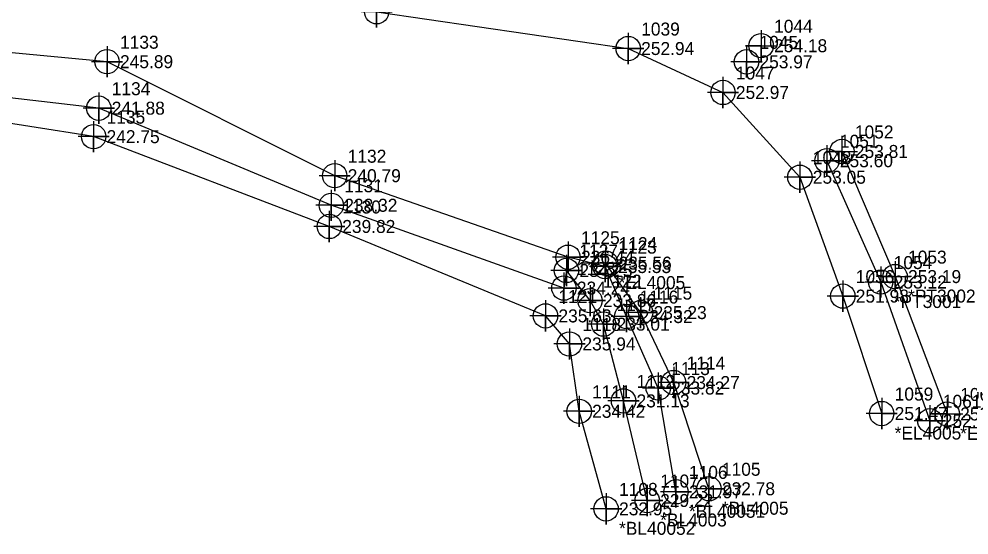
# Model space of a CAD drawing. Extents: x 2130962 to 2131465, y 643052 to 644206.
# Drawn here: x 2131077.2 to 2131260.2, y 643052.4 to 643151.7 of the extents above; entities that cross this region are included whole.
import ezdxf

# ---------------------------------------------------------------- set-up
doc = ezdxf.new("R2010")
doc.units = 0
for name, color, linetype in [('Exist DTM Breakline', 7, 'Continuous'), ('Exist DTM Breakline Cogo Comment', 7, 'Continuous'), ('Exist DTM Breakline Cogo Elevation', 7, 'Continuous'), ('Exist DTM Breakline Cogo Number', 7, 'Continuous'), ('Exist DTM Breakline Cogo Point CELL', 7, 'Continuous'), ('Exist DTM Drainline', 7, 'Continuous'), ('Exist DTM Drainline Cogo Comment', 7, 'Continuous'), ('Exist DTM Drainline Cogo Elevation', 7, 'Continuous'), ('Exist DTM Drainline Cogo Number', 7, 'Continuous'), ('Exist DTM Drainline Cogo Point CELL', 7, 'Continuous'), ('Exist Roads EOP', 7, 'Continuous'), ('Exist Roads EOP Cogo Comment', 7, 'Continuous'), ('Exist Roads EOP Cogo Elevation', 7, 'Continuous'), ('Exist Roads EOP Cogo Number', 7, 'Continuous'), ('Exist Roads EOP Cogo Point CELL', 7, 'Continuous'), ('Exist Roads EOT', 7, 'Continuous'), ('Exist Roads EOT Cogo Comment', 7, 'Continuous'), ('Exist Roads EOT Cogo Elevation', 7, 'Continuous'), ('Exist Roads EOT Cogo Number', 7, 'Continuous'), ('Exist Roads EOT Cogo Point CELL', 7, 'Continuous')]:
    doc.layers.add(name, color=color, linetype=linetype)

msp = doc.modelspace()

# ---------------------------------------------------------------- linework, layer by layer
at = {"layer": 'Exist DTM Breakline'}
for points in [[(2130997.5489, 643165.941), (2131045.6664, 643161.7962), (2131094.7686, 643157.2786), (2131146.0902, 643153.1147), (2131194.5413, 643146.0346), (2131212.7846, 643137.5737), (2131227.5943, 643121.2545), (2131235.8712, 643098.3644), (2131243.3589, 643075.7514)], [(2131203.7387, 643060.6768), (2131200.323, 643080.6622), (2131194.2334, 643094.4284), (2131190.0903, 643104.0511), (2131182.9576, 643105.8495), (2131138.023, 643121.5465), (2131094.1742, 643143.5026), (2131040.5455, 643148.5531), (2130995.6405, 643153.3049)], [(2131190.282, 643057.3997), (2131185.0957, 643076.1853), (2131183.224, 643089.154), (2131178.6092, 643094.5527), (2131136.9713, 643111.7747), (2131091.5821, 643129.064), (2131042.4244, 643136.794), (2130995.734, 643143.071)], [(2131210.0876, 643061.2695), (2131203.2966, 643081.7186), (2131196.9334, 643095.1899), (2131190.1951, 643104.7138)]]:
    msp.add_lwpolyline(points, dxfattribs=at)
at = {"layer": 'Exist DTM Breakline Cogo Point CELL'}
for points in [[(2131146.0902, 643156.1147), (2131146.0902, 643150.1147), (2131146.0902, 643153.1147), (2131149.0902, 643153.1147), (2131143.0902, 643153.1147)], [(2131194.5413, 643149.0346), (2131194.5413, 643143.0346), (2131194.5413, 643146.0346), (2131197.5413, 643146.0346), (2131191.5413, 643146.0346)], [(2131094.1742, 643146.5026), (2131094.1742, 643140.5026), (2131094.1742, 643143.5026), (2131097.1742, 643143.5026), (2131091.1742, 643143.5026)], [(2131212.7846, 643140.5737), (2131212.7846, 643134.5737), (2131212.7846, 643137.5737), (2131215.7846, 643137.5737), (2131209.7846, 643137.5737)], [(2131091.5821, 643132.064), (2131091.5821, 643126.064), (2131091.5821, 643129.064), (2131094.5821, 643129.064), (2131088.5821, 643129.064)], [(2131138.023, 643124.5465), (2131138.023, 643118.5465), (2131138.023, 643121.5465), (2131141.023, 643121.5465), (2131135.023, 643121.5465)], [(2131227.5943, 643124.2545), (2131227.5943, 643118.2545), (2131227.5943, 643121.2545), (2131230.5943, 643121.2545), (2131224.5943, 643121.2545)], [(2131136.9713, 643114.7747), (2131136.9713, 643108.7747), (2131136.9713, 643111.7747), (2131139.9713, 643111.7747), (2131133.9713, 643111.7747)], [(2131182.9576, 643108.8495), (2131182.9576, 643102.8495), (2131182.9576, 643105.8495), (2131185.9576, 643105.8495), (2131179.9576, 643105.8495)], [(2131190.0903, 643107.0511), (2131190.0903, 643101.0511), (2131190.0903, 643104.0511), (2131193.0903, 643104.0511), (2131187.0903, 643104.0511)], [(2131190.1951, 643107.7138), (2131190.1951, 643101.7138), (2131190.1951, 643104.7138), (2131193.1951, 643104.7138), (2131187.1951, 643104.7138)], [(2131235.8712, 643101.3644), (2131235.8712, 643095.3644), (2131235.8712, 643098.3644), (2131238.8712, 643098.3644), (2131232.8712, 643098.3644)], [(2131178.6092, 643097.5527), (2131178.6092, 643091.5527), (2131178.6092, 643094.5527), (2131181.6092, 643094.5527), (2131175.6092, 643094.5527)], [(2131194.2334, 643097.4284), (2131194.2334, 643091.4284), (2131194.2334, 643094.4284), (2131197.2334, 643094.4284), (2131191.2334, 643094.4284)], [(2131196.9334, 643098.1899), (2131196.9334, 643092.1899), (2131196.9334, 643095.1899), (2131199.9334, 643095.1899), (2131193.9334, 643095.1899)], [(2131183.224, 643092.154), (2131183.224, 643086.154), (2131183.224, 643089.154), (2131186.224, 643089.154), (2131180.224, 643089.154)], [(2131203.2966, 643084.7186), (2131203.2966, 643078.7186), (2131203.2966, 643081.7186), (2131206.2966, 643081.7186), (2131200.2966, 643081.7186)], [(2131200.323, 643083.6622), (2131200.323, 643077.6622), (2131200.323, 643080.6622), (2131203.323, 643080.6622), (2131197.323, 643080.6622)], [(2131185.0957, 643079.1853), (2131185.0957, 643073.1853), (2131185.0957, 643076.1853), (2131188.0957, 643076.1853), (2131182.0957, 643076.1853)], [(2131243.3589, 643078.7514), (2131243.3589, 643072.7514), (2131243.3589, 643075.7514), (2131246.3589, 643075.7514), (2131240.3589, 643075.7514)], [(2131210.0876, 643064.2695), (2131210.0876, 643058.2695), (2131210.0876, 643061.2695), (2131213.0876, 643061.2695), (2131207.0876, 643061.2695)], [(2131203.7387, 643063.6768), (2131203.7387, 643057.6768), (2131203.7387, 643060.6768), (2131206.7387, 643060.6768), (2131200.7387, 643060.6768)], [(2131190.282, 643060.3997), (2131190.282, 643054.3997), (2131190.282, 643057.3997), (2131193.282, 643057.3997), (2131187.282, 643057.3997)]]:
    msp.add_lwpolyline(points, dxfattribs=at)
for centre in [(2131146.0902, 643153.1147), (2131194.5413, 643146.0346), (2131094.1742, 643143.5026), (2131212.7846, 643137.5737), (2131091.5821, 643129.064), (2131138.023, 643121.5465), (2131227.5943, 643121.2545), (2131136.9713, 643111.7747), (2131182.9576, 643105.8495), (2131190.0903, 643104.0511), (2131190.1951, 643104.7138), (2131235.8712, 643098.3644), (2131196.9334, 643095.1899), (2131178.6092, 643094.5527), (2131194.2334, 643094.4284), (2131183.224, 643089.154), (2131200.323, 643080.6622), (2131203.2966, 643081.7186), (2131185.0957, 643076.1853), (2131243.3589, 643075.7514), (2131203.7387, 643060.6768), (2131210.0876, 643061.2695), (2131190.282, 643057.3997)]:
    msp.add_circle(centre, 2.344, dxfattribs=at)
at = {"layer": 'Exist DTM Drainline'}
msp.add_lwpolyline([(2131198.1997, 643059.006), (2131193.6429, 643078.1873), (2131189.8038, 643092.9639), (2131187.1852, 643097.4954), (2131182.6436, 643103.2956), (2131182.1533, 643099.9067), (2131137.3651, 643115.851), (2131092.5788, 643134.5516), (2131042.2635, 643140.3935), (2130996.1192, 643147.7639)], dxfattribs=at)
at = {"layer": 'Exist DTM Drainline Cogo Point CELL'}
for points in [[(2131092.5788, 643137.5516), (2131092.5788, 643131.5516), (2131092.5788, 643134.5516), (2131095.5788, 643134.5516), (2131089.5788, 643134.5516)], [(2131137.3651, 643118.851), (2131137.3651, 643112.851), (2131137.3651, 643115.851), (2131140.3651, 643115.851), (2131134.3651, 643115.851)], [(2131182.6436, 643106.2956), (2131182.6436, 643100.2956), (2131182.6436, 643103.2956), (2131185.6436, 643103.2956), (2131179.6436, 643103.2956)], [(2131182.1533, 643102.9067), (2131182.1533, 643096.9067), (2131182.1533, 643099.9067), (2131185.1533, 643099.9067), (2131179.1533, 643099.9067)], [(2131187.1852, 643100.4954), (2131187.1852, 643094.4954), (2131187.1852, 643097.4954), (2131190.1852, 643097.4954), (2131184.1852, 643097.4954)], [(2131189.8038, 643095.9639), (2131189.8038, 643089.9639), (2131189.8038, 643092.9639), (2131192.8038, 643092.9639), (2131186.8038, 643092.9639)], [(2131193.6429, 643081.1873), (2131193.6429, 643075.1873), (2131193.6429, 643078.1873), (2131196.6429, 643078.1873), (2131190.6429, 643078.1873)], [(2131198.1997, 643062.006), (2131198.1997, 643056.006), (2131198.1997, 643059.006), (2131201.1997, 643059.006), (2131195.1997, 643059.006)]]:
    msp.add_lwpolyline(points, dxfattribs=at)
for centre in [(2131092.5788, 643134.5516), (2131137.3651, 643115.851), (2131182.6436, 643103.2956), (2131182.1533, 643099.9067), (2131187.1852, 643097.4954), (2131189.8038, 643092.9639), (2131193.6429, 643078.1873), (2131198.1997, 643059.006)]:
    msp.add_circle(centre, 2.344, dxfattribs=at)
at = {"layer": 'Exist Roads EOP'}
msp.add_lwpolyline([(2131232.8113, 643124.4316), (2131243.1743, 643101.0702), (2131252.6325, 643074.3547)], dxfattribs=at)
at = {"layer": 'Exist Roads EOP Cogo Point CELL'}
for points in [[(2131217.3223, 643146.473), (2131217.3223, 643140.473), (2131217.3223, 643143.473), (2131220.3223, 643143.473), (2131214.3223, 643143.473)], [(2131232.8113, 643127.4316), (2131232.8113, 643121.4316), (2131232.8113, 643124.4316), (2131235.8113, 643124.4316), (2131229.8113, 643124.4316)], [(2131243.1743, 643104.0702), (2131243.1743, 643098.0702), (2131243.1743, 643101.0702), (2131246.1743, 643101.0702), (2131240.1743, 643101.0702)], [(2131252.6325, 643077.3547), (2131252.6325, 643071.3547), (2131252.6325, 643074.3547), (2131255.6325, 643074.3547), (2131249.6325, 643074.3547)]]:
    msp.add_lwpolyline(points, dxfattribs=at)
for centre in [(2131217.3223, 643143.473), (2131232.8113, 643124.4316), (2131243.1743, 643101.0702), (2131252.6325, 643074.3547)]:
    msp.add_circle(centre, 2.344, dxfattribs=at)
at = {"layer": 'Exist Roads EOT'}
msp.add_lwpolyline([(2131235.6934, 643126.2176), (2131245.9361, 643102.1206), (2131255.9743, 643075.6707)], dxfattribs=at)
at = {"layer": 'Exist Roads EOT Cogo Point CELL'}
for points in [[(2131220.1404, 643149.5724), (2131220.1404, 643143.5724), (2131220.1404, 643146.5724), (2131217.1404, 643146.5724), (2131223.1404, 643146.5724)], [(2131235.6934, 643129.2176), (2131235.6934, 643123.2176), (2131235.6934, 643126.2176), (2131232.6934, 643126.2176), (2131238.6934, 643126.2176)], [(2131245.9361, 643105.1206), (2131245.9361, 643099.1206), (2131245.9361, 643102.1206), (2131242.9361, 643102.1206), (2131248.9361, 643102.1206)], [(2131255.9743, 643078.6707), (2131255.9743, 643072.6707), (2131255.9743, 643075.6707), (2131252.9743, 643075.6707), (2131258.9743, 643075.6707)]]:
    msp.add_lwpolyline(points, dxfattribs=at)
for centre in [(2131220.1404, 643146.5724), (2131235.6934, 643126.2176), (2131245.9361, 643102.1206), (2131255.9743, 643075.6707)]:
    msp.add_circle(centre, 2.344, dxfattribs=at)

# ---------------------------------------------------------------- texts
at = {"layer": 'Exist DTM Breakline Cogo Comment'}
for s, p in [('*EL4005', (2131192.6951, 643099.7138)), ('*EL4005', (2131245.8589, 643070.7514)), ('*BL4005', (2131212.5876, 643056.2695)), ('*BL40051', (2131206.2387, 643055.6768)), ('*BL40052', (2131192.782, 643052.3997))]:
    msp.add_text(s, height=2.5, dxfattribs=at).set_placement(p)
at = {"layer": 'Exist DTM Breakline Cogo Elevation'}
for s, p in [('252.94', (2131197.0413, 643144.7846)), ('245.89', (2131096.6742, 643142.2526)), ('252.97', (2131215.2846, 643136.3237)), ('242.75', (2131094.0821, 643127.814)), ('240.79', (2131140.523, 643120.2965)), ('253.05', (2131230.0943, 643120.0045)), ('239.82', (2131139.4713, 643110.5247)), ('236.44', (2131185.4576, 643104.5995)), ('235.53', (2131192.5903, 643102.8011)), ('235.56', (2131192.6951, 643103.4638)), ('251.98', (2131238.3712, 643097.1144)), ('235.63', (2131181.1092, 643093.3027)), ('234.32', (2131196.7334, 643093.1784)), ('235.23', (2131199.4334, 643093.9399)), ('235.94', (2131185.724, 643087.904)), ('234.27', (2131205.7966, 643080.4686)), ('233.82', (2131202.823, 643079.4122)), ('234.42', (2131187.5957, 643074.9353)), ('251.47', (2131245.8589, 643074.5014)), ('232.78', (2131212.5876, 643060.0195)), ('231.97', (2131206.2387, 643059.4268)), ('232.95', (2131192.782, 643056.1497))]:
    msp.add_text(s, height=2.5, dxfattribs=at).set_placement(p)
at = {"layer": 'Exist DTM Breakline Cogo Number'}
for s, p in [('1039', (2131197.0413, 643148.5346)), ('1133', (2131096.6742, 643146.0026)), ('1047', (2131215.2846, 643140.0737)), ('1135', (2131094.0821, 643131.564)), ('1132', (2131140.523, 643124.0465)), ('1048', (2131230.0943, 643123.7545)), ('1130', (2131139.4713, 643114.2747)), ('1125', (2131185.4576, 643108.3495)), ('1124', (2131192.6951, 643107.2138)), ('1123', (2131192.5903, 643106.5511)), ('1056', (2131238.3712, 643100.8644)), ('1121', (2131181.1092, 643097.0527)), ('1116', (2131196.7334, 643096.9284)), ('1115', (2131199.4334, 643097.6899)), ('1118', (2131185.724, 643091.654)), ('1114', (2131205.7966, 643084.2186)), ('1113', (2131202.823, 643083.1622)), ('1111', (2131187.5957, 643078.6853)), ('1059', (2131245.8589, 643078.2514)), ('1105', (2131212.5876, 643063.7695)), ('1106', (2131206.2387, 643063.1768)), ('1108', (2131192.782, 643059.8997))]:
    msp.add_text(s, height=2.5, dxfattribs=at).set_placement(p)
at = {"layer": 'Exist DTM Drainline Cogo Comment'}
msp.add_text('*BL4003', height=2.5, dxfattribs=at).set_placement((2131200.6997, 643054.006))
at = {"layer": 'Exist DTM Drainline Cogo Elevation'}
for s, p in [('241.88', (2131095.0788, 643133.3016)), ('238.32', (2131139.8651, 643114.601)), ('234.25', (2131185.1436, 643102.0456)), ('234.24', (2131184.6533, 643098.6567)), ('233.86', (2131189.6852, 643096.2454)), ('233.01', (2131192.3038, 643091.7139)), ('231.13', (2131196.1429, 643076.9373)), ('229.22', (2131200.6997, 643057.756))]:
    msp.add_text(s, height=2.5, dxfattribs=at).set_placement(p)
at = {"layer": 'Exist DTM Drainline Cogo Number'}
for s, p in [('1134', (2131095.0788, 643137.0516)), ('1131', (2131139.8651, 643118.351)), ('1127', (2131185.1436, 643105.7956)), ('1128', (2131184.6533, 643102.4067)), ('1122', (2131189.6852, 643099.9954)), ('1117', (2131192.3038, 643095.4639)), ('1112', (2131196.1429, 643080.6873)), ('1107', (2131200.6997, 643061.506))]:
    msp.add_text(s, height=2.5, dxfattribs=at).set_placement(p)
at = {"layer": 'Exist Roads EOP Cogo Comment'}
msp.add_text('*PT3001', height=2.5, dxfattribs=at).set_placement((2131245.6743, 643096.0702))
at = {"layer": 'Exist Roads EOP Cogo Elevation'}
for s, p in [('253.97', (2131219.8223, 643142.223)), ('253.60', (2131235.3113, 643123.1816)), ('253.12', (2131245.6743, 643099.8202)), ('252.68', (2131255.1325, 643073.1047))]:
    msp.add_text(s, height=2.5, dxfattribs=at).set_placement(p)
at = {"layer": 'Exist Roads EOP Cogo Number'}
for s, p in [('1045', (2131219.8223, 643145.973)), ('1051', (2131235.3113, 643126.9316)), ('1054', (2131245.6743, 643103.5702)), ('1061', (2131255.1325, 643076.8547))]:
    msp.add_text(s, height=2.5, dxfattribs=at).set_placement(p)
at = {"layer": 'Exist Roads EOT Cogo Comment'}
for s, p in [('*PT3002', (2131248.4361, 643097.1206)), ('*EL3002', (2131258.4743, 643070.6707))]:
    msp.add_text(s, height=2.5, dxfattribs=at).set_placement(p)
at = {"layer": 'Exist Roads EOT Cogo Elevation'}
for s, p in [('254.18', (2131222.6404, 643145.3224)), ('253.81', (2131238.1934, 643124.9676)), ('253.19', (2131248.4361, 643100.8706)), ('252.78', (2131258.4743, 643074.4207))]:
    msp.add_text(s, height=2.5, dxfattribs=at).set_placement(p)
at = {"layer": 'Exist Roads EOT Cogo Number'}
for s, p in [('1044', (2131222.6404, 643149.0724)), ('1052', (2131238.1934, 643128.7176)), ('1053', (2131248.4361, 643104.6206)), ('1062', (2131258.4743, 643078.1707))]:
    msp.add_text(s, height=2.5, dxfattribs=at).set_placement(p)

doc.saveas('drawing.dxf')
